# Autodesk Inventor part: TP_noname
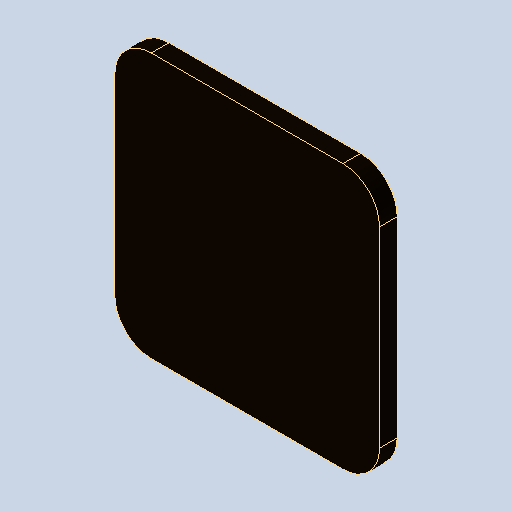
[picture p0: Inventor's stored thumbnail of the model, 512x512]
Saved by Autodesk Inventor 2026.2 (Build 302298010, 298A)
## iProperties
Created: 2026-10
Part Number: TP_noname
Material: Générique
Document SubType Name: Modeling
Designer: mel
Density: 1 g/cm^3
Appearance: Par défaut
Author: mel
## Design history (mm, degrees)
feature "Base1"
node "Solide1"
